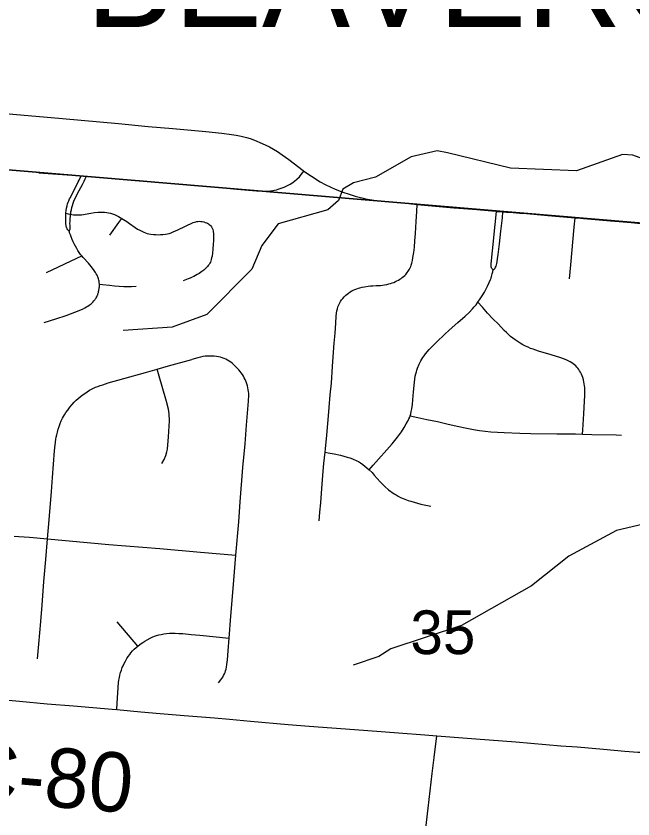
# Model space of a CAD drawing. Extents: x 0 to 34, y 0 to 22.
# Drawn here: x 5.745 to 6.336, y 14.804 to 15.574 of the extents above; entities that cross this region are included whole.
import ezdxf

# ---------------------------------------------------------------- set-up
doc = ezdxf.new("R2010")
doc.units = 0
for name, color, linetype in [('GM_X_City_Street', 7, 'Continuous'), ('GM_X_Corporation', 7, 'Continuous'), ('GM_X_Corporation_Text', 7, 'Continuous'), ('GM_X_County_Road', 7, 'Continuous'), ('GM_X_County_Road_Text', 7, 'Continuous'), ('GM_X_Minor_River', 7, 'Continuous'), ('GM_X_Section_Text', 7, 'Continuous')]:
    doc.layers.add(name, color=color, linetype=linetype)

msp = doc.modelspace()

# ---------------------------------------------------------------- linework, layer by layer
at = {"layer": 'GM_X_City_Street'}
msp.add_line((5.86155, 14.97007), (5.84193, 14.99325), dxfattribs=at)
for points in [[(5.76659, 15.42355), (5.80727, 15.42065), (5.81247, 15.42013), (5.84403, 15.41751), (5.86325, 15.41599), (5.8886, 15.41382), (5.91709, 15.41134), (5.92823, 15.41045), (5.94057, 15.40931), (5.9566, 15.40789), (5.97516, 15.40616), (5.98205, 15.40588), (5.98428, 15.40587), (5.98644, 15.40592), (5.9886, 15.40617), (5.99088, 15.40655), (5.99267, 15.40685), (5.99439, 15.40728), (5.99612, 15.40778), (5.99791, 15.40833), (5.99988, 15.40901), (6.00173, 15.40981), (6.0037, 15.41067), (6.00568, 15.41166), (6.00753, 15.41258), (6.00916, 15.41359), (6.01176, 15.41547), (6.014, 15.41739), (6.0164, 15.41967), (6.01814, 15.42182), (6.02084, 15.42514)], [(5.79274, 15.38468), (5.79298, 15.38724), (5.79331, 15.38946), (5.79376, 15.39168), (5.79431, 15.39372), (5.79479, 15.39525), (5.79535, 15.39665), (5.79618, 15.39842), (5.79703, 15.39995), (5.79816, 15.40208), (5.79962, 15.4049), (5.80451, 15.41482), (5.80527, 15.4163), (5.80727, 15.42065)], [(5.79719, 15.38386), (5.79731, 15.38466), (5.79751, 15.38597), (5.79792, 15.38802), (5.79842, 15.39026), (5.79897, 15.39222), (5.79961, 15.39429), (5.80035, 15.39632), (5.8013, 15.3986), (5.80233, 15.40086), (5.80319, 15.40243), (5.80547, 15.40644), (5.80852, 15.41224), (5.8101, 15.41541), (5.81118, 15.41757), (5.81247, 15.42013)], [(6.0353, 15.09014), (6.03612, 15.09844), (6.03697, 15.10736), (6.03805, 15.12094), (6.03931, 15.1376), (6.03992, 15.145), (6.04099, 15.15577), (6.04133, 15.15912), (6.0427, 15.17205), (6.04436, 15.19055), (6.04495, 15.19855), (6.04605, 15.21086), (6.04704, 15.22196), (6.0481, 15.23789), (6.04885, 15.24715), (6.04988, 15.26012), (6.05059, 15.26999), (6.0512, 15.27926), (6.05166, 15.28599), (6.05199, 15.28885), (6.0524, 15.29127), (6.05285, 15.29325), (6.05335, 15.29493), (6.05388, 15.29646), (6.05444, 15.2977), (6.05511, 15.29904), (6.0559, 15.30027), (6.05692, 15.30168), (6.05813, 15.30311), (6.05943, 15.30467), (6.06103, 15.3062), (6.06215, 15.30713), (6.06354, 15.30825), (6.06514, 15.30936), (6.06668, 15.31037), (6.0681, 15.31108), (6.06966, 15.31179), (6.07145, 15.31242), (6.07305, 15.31292), (6.07449, 15.31333), (6.07654, 15.31386), (6.07893, 15.31432), (6.08222, 15.31481), (6.08452, 15.31509), (6.0869, 15.31527), (6.08998, 15.31534), (6.09266, 15.31542), (6.09418, 15.31555), (6.09594, 15.31575), (6.09808, 15.31608), (6.10037, 15.31653), (6.10224, 15.31699), (6.10379, 15.31743), (6.10522, 15.31791), (6.10687, 15.3185), (6.10855, 15.3192), (6.10991, 15.31986), (6.11136, 15.32065), (6.1127, 15.32142), (6.11408, 15.32235), (6.11504, 15.3231), (6.11606, 15.324), (6.11743, 15.3252), (6.11829, 15.3261), (6.11903, 15.32693), (6.11982, 15.32787), (6.12072, 15.32915), (6.12146, 15.33022), (6.1221, 15.3313), (6.12265, 15.33243), (6.12318, 15.33367), (6.12368, 15.33511), (6.12413, 15.33673), (6.12471, 15.33942), (6.12523, 15.34227), (6.126, 15.34704), (6.12663, 15.35216), (6.12715, 15.35839), (6.12761, 15.36519), (6.12848, 15.37695), (6.12904, 15.38634), (6.12945, 15.39321)], [(5.79587, 15.36752), (5.7949, 15.36835), (5.79437, 15.36896), (5.79393, 15.36965), (5.79359, 15.37041), (5.79329, 15.37127), (5.79305, 15.37201), (5.79289, 15.37283), (5.79268, 15.37452), (5.79249, 15.37692), (5.79244, 15.37862), (5.79253, 15.38181), (5.79274, 15.38468)], [(5.79274, 15.38468), (5.79487, 15.3843), (5.79719, 15.38386)], [(5.79587, 15.36752), (5.79618, 15.36818), (5.79642, 15.3688), (5.79659, 15.3695), (5.79667, 15.37016), (5.79675, 15.37082), (5.79675, 15.37184), (5.79667, 15.37295), (5.79657, 15.37489), (5.79659, 15.37694), (5.79678, 15.37978), (5.79695, 15.3819), (5.79719, 15.38386)], [(5.79719, 15.38386), (5.79844, 15.38361), (5.80002, 15.3833), (5.80162, 15.38314), (5.8033, 15.38306), (5.80532, 15.38309), (5.8075, 15.38335), (5.81668, 15.3849), (5.81999, 15.38532), (5.82352, 15.38562), (5.8257, 15.38573), (5.82793, 15.38577), (5.82974, 15.38569), (5.83174, 15.38551), (5.8336, 15.38519), (5.8355, 15.38477), (5.83742, 15.38416), (5.83913, 15.38353), (5.84116, 15.3826), (5.84312, 15.3816), (5.84474, 15.38071), (5.84638, 15.37973)], [(6.2021, 15.33056), (6.20143, 15.33124), (6.20102, 15.33173), (6.2007, 15.33233), (6.20036, 15.33346), (6.20025, 15.33472), (6.20032, 15.33597), (6.2006, 15.33934), (6.20157, 15.34857), (6.20409, 15.37385), (6.20462, 15.37984), (6.20519, 15.38656)], [(6.2021, 15.33056), (6.20309, 15.33122), (6.20399, 15.33209), (6.20452, 15.33303), (6.20498, 15.33406), (6.20539, 15.33526), (6.20571, 15.33665), (6.206, 15.33825), (6.20645, 15.34117), (6.20703, 15.34516), (6.20815, 15.35529), (6.20964, 15.36756), (6.21082, 15.3779), (6.21102, 15.38035), (6.21149, 15.38605)], [(5.83487, 15.36366), (5.84347, 15.3757), (5.84638, 15.37973)], [(5.84638, 15.37973), (5.84799, 15.37875), (5.8509, 15.37677), (5.85363, 15.37481), (5.85916, 15.37093), (5.86142, 15.36957), (5.86336, 15.36846), (5.86533, 15.36748), (5.86719, 15.36663), (5.86886, 15.366), (5.87059, 15.36545), (5.87223, 15.36506), (5.87411, 15.36476), (5.87651, 15.36443), (5.87896, 15.36423), (5.88103, 15.36415), (5.88321, 15.36422), (5.88555, 15.3644), (5.88804, 15.36467), (5.88987, 15.36501), (5.89156, 15.36541), (5.89356, 15.36604), (5.89556, 15.36678), (5.9, 15.3688), (5.90728, 15.37234), (5.91462, 15.37576), (5.91709, 15.37662), (5.91814, 15.37685), (5.91909, 15.37693), (5.92049, 15.37697), (5.92189, 15.37689), (5.92332, 15.37668), (5.92491, 15.37635), (5.92624, 15.37599), (5.92743, 15.37557), (5.92838, 15.37512), (5.92922, 15.37464), (5.93006, 15.37405), (5.93084, 15.37339), (5.93159, 15.37266), (5.93216, 15.37184), (5.93265, 15.37093), (5.9331, 15.3699), (5.93343, 15.369), (5.93368, 15.36793), (5.93388, 15.36678), (5.93402, 15.36544), (5.93413, 15.36415), (5.93417, 15.36296), (5.93417, 15.36168), (5.93416, 15.36037), (5.93405, 15.35802), (5.93385, 15.35536), (5.93335, 15.35001), (5.93267, 15.34358), (5.93232, 15.34187), (5.93198, 15.34044), (5.93154, 15.33904), (5.93113, 15.33799), (5.93052, 15.33673), (5.92991, 15.33567), (5.92912, 15.33452), (5.92837, 15.33355), (5.92747, 15.33258), (5.92652, 15.33171), (5.92476, 15.33028), (5.92304, 15.32896), (5.92156, 15.32794), (5.92024, 15.32712), (5.91859, 15.32605), (5.91699, 15.32515), (5.91539, 15.32424), (5.91366, 15.32337), (5.91186, 15.32255), (5.90988, 15.32173), (5.90507, 15.31993)], [(6.27522, 15.32185), (6.27644, 15.3353), (6.27984, 15.37133), (6.28069, 15.38034)], [(5.80783, 15.34385), (5.80667, 15.34533), (5.80539, 15.34708), (5.80418, 15.34894), (5.80302, 15.35093), (5.8018, 15.3531), (5.80065, 15.35536), (5.79976, 15.35735), (5.79874, 15.35966), (5.79777, 15.36197), (5.79694, 15.3641), (5.79624, 15.366), (5.79605, 15.3667), (5.79587, 15.36752)], [(5.77407, 15.32788), (5.80299, 15.34152), (5.80783, 15.34385)], [(5.82473, 15.31686), (5.82463, 15.31826), (5.82446, 15.31951), (5.82422, 15.32068), (5.82388, 15.32191), (5.82358, 15.32282), (5.82327, 15.3237), (5.8229, 15.32457), (5.82251, 15.32536), (5.82181, 15.32673), (5.82098, 15.32804), (5.81968, 15.32994), (5.81812, 15.33209), (5.81423, 15.33691), (5.8092, 15.34233), (5.80783, 15.34385)], [(6.0833, 15.13901), (6.08721, 15.14346), (6.10524, 15.16397), (6.1105, 15.17016), (6.11424, 15.1752), (6.11693, 15.17945), (6.11889, 15.18294), (6.12033, 15.18543), (6.12139, 15.18766), (6.12213, 15.18941), (6.12254, 15.19056), (6.1231, 15.19248), (6.12361, 15.19478), (6.12408, 15.19744), (6.12468, 15.20157), (6.12526, 15.20611), (6.12581, 15.21358), (6.1266, 15.22281), (6.12701, 15.22576), (6.12754, 15.22873), (6.12795, 15.23077), (6.12851, 15.23279), (6.12906, 15.23443), (6.12973, 15.23618), (6.13132, 15.24002), (6.13296, 15.24345), (6.13383, 15.24503), (6.1348, 15.24656), (6.13597, 15.24824), (6.1373, 15.25), (6.14096, 15.25411), (6.14788, 15.26118), (6.15588, 15.2689), (6.16002, 15.27263), (6.16834, 15.28005), (6.17527, 15.28624), (6.179, 15.28975), (6.18243, 15.2932), (6.18408, 15.29506), (6.1857, 15.29694), (6.18758, 15.29938), (6.18977, 15.30257), (6.19166, 15.30574), (6.19372, 15.30915), (6.19523, 15.31182), (6.1968, 15.31474), (6.19836, 15.31824), (6.19959, 15.32119), (6.20009, 15.32255), (6.20056, 15.32405), (6.20095, 15.3253), (6.20132, 15.32657), (6.20161, 15.32764), (6.2018, 15.32857), (6.20197, 15.32954), (6.2021, 15.33056)], [(5.77177, 15.28017), (5.78306, 15.28353), (5.79303, 15.28675), (5.80118, 15.28989), (5.80862, 15.29298), (5.81065, 15.29397), (5.81249, 15.29494), (5.81373, 15.29573), (5.81505, 15.29669), (5.81673, 15.29804), (5.81834, 15.29952), (5.81944, 15.30066), (5.8204, 15.30183), (5.82084, 15.30239), (5.82133, 15.30309), (5.82175, 15.30379), (5.82235, 15.30478), (5.82261, 15.30543), (5.8229, 15.30609), (5.82312, 15.30668), (5.82339, 15.30741), (5.82359, 15.3081), (5.82384, 15.30888), (5.82404, 15.30975), (5.82421, 15.31057), (5.82437, 15.31151), (5.8245, 15.31242), (5.82461, 15.31335), (5.82471, 15.31426), (5.82473, 15.31516), (5.82476, 15.316), (5.82473, 15.31686)], [(5.82473, 15.31686), (5.82788, 15.3165), (5.83429, 15.31582), (5.8391, 15.31532), (5.84366, 15.31496), (5.84815, 15.31466), (5.85155, 15.31458), (5.85537, 15.31464), (5.85984, 15.31486)], [(6.28775, 15.17308), (6.288, 15.1772), (6.28896, 15.19257), (6.28959, 15.20473), (6.28984, 15.21024), (6.28992, 15.21324), (6.28997, 15.21597), (6.28992, 15.21772), (6.2898, 15.21928), (6.28951, 15.22125), (6.28918, 15.22317), (6.28869, 15.2252), (6.28806, 15.22725), (6.28742, 15.22898), (6.28673, 15.23063), (6.28585, 15.23235), (6.28501, 15.2338), (6.28417, 15.23502), (6.28326, 15.23623), (6.28232, 15.23732), (6.28124, 15.23842), (6.28018, 15.23938), (6.27896, 15.24035), (6.27751, 15.24135), (6.27594, 15.24232), (6.27406, 15.24332), (6.27216, 15.24422), (6.26966, 15.24529), (6.26704, 15.24623), (6.25763, 15.24913), (6.24571, 15.25262), (6.2429, 15.25347), (6.24033, 15.25435), (6.23789, 15.25528), (6.23567, 15.25626), (6.23304, 15.2575), (6.2306, 15.25879), (6.22794, 15.26029), (6.22521, 15.26203), (6.22309, 15.26346), (6.22109, 15.26492), (6.21878, 15.26675), (6.21673, 15.26854), (6.21479, 15.27045), (6.21271, 15.2725), (6.20711, 15.27833), (6.20189, 15.28368), (6.19681, 15.28909), (6.19189, 15.29461), (6.18758, 15.29938)], [(5.76539, 14.95782), (5.76682, 14.97203), (5.76855, 14.99371), (5.76981, 15.00919), (5.77162, 15.03209), (5.77339, 15.05312), (5.77506, 15.07278), (5.77646, 15.09088), (5.77878, 15.11806), (5.77984, 15.13168), (5.78185, 15.15708), (5.78305, 15.16819), (5.78339, 15.17033), (5.78381, 15.17249), (5.78446, 15.1751), (5.78525, 15.17791), (5.78606, 15.18036), (5.78714, 15.18318), (5.78824, 15.18583), (5.78943, 15.18827), (5.79127, 15.1915), (5.79272, 15.19368), (5.79444, 15.19609), (5.7965, 15.19881), (5.79871, 15.20141), (5.80065, 15.20358), (5.8025, 15.2055), (5.80427, 15.20712), (5.80619, 15.20882), (5.80821, 15.2104), (5.81065, 15.21217), (5.81298, 15.2137), (5.81537, 15.21516), (5.81717, 15.2162), (5.8192, 15.21719), (5.82104, 15.21801), (5.8232, 15.21889), (5.82547, 15.21969), (5.8279, 15.22048), (5.83321, 15.22222), (5.84812, 15.22645), (5.86906, 15.23212), (5.87996, 15.23523), (5.89111, 15.2384), (5.91343, 15.2447)], [(5.93897, 14.93489), (5.94115, 14.93768), (5.9421, 14.939), (5.94296, 14.94036), (5.94378, 14.94175), (5.94463, 14.94338), (5.94522, 14.94471), (5.94573, 14.94627), (5.94621, 14.94804), (5.94661, 14.94987), (5.94699, 14.95235), (5.94744, 14.95675), (5.94818, 14.96547), (5.94908, 14.97764), (5.95077, 14.99875), (5.95297, 15.02536), (5.95566, 15.05702), (5.95825, 15.08908), (5.95967, 15.10827), (5.96233, 15.14106), (5.96433, 15.16392), (5.9658, 15.18185), (5.96761, 15.20474), (5.96791, 15.21032), (5.96791, 15.21212), (5.96773, 15.21404), (5.96749, 15.21565), (5.96713, 15.21758), (5.96663, 15.21939), (5.96605, 15.22128), (5.96536, 15.2233), (5.96446, 15.22532), (5.96364, 15.22699), (5.96278, 15.22864), (5.96178, 15.23016), (5.96073, 15.23175), (5.95957, 15.2332), (5.95836, 15.23462), (5.95718, 15.23595), (5.95586, 15.23727), (5.95397, 15.23912), (5.95225, 15.24068), (5.95056, 15.24212), (5.94921, 15.24306), (5.94768, 15.24402), (5.94608, 15.24479), (5.94429, 15.24559), (5.94255, 15.24619), (5.9407, 15.24674), (5.93885, 15.24713), (5.93702, 15.24747), (5.93478, 15.24771), (5.93269, 15.24786), (5.93042, 15.24792), (5.92835, 15.24783), (5.92619, 15.24767), (5.92403, 15.24732), (5.92167, 15.24685), (5.91918, 15.24626), (5.91343, 15.2447)], [(5.88473, 15.14486), (5.88671, 15.14879), (5.88841, 15.15253), (5.88938, 15.15608), (5.88989, 15.15883), (5.89106, 15.17047), (5.89189, 15.18595), (5.89152, 15.19246), (5.89082, 15.19712), (5.88906, 15.20425), (5.88124, 15.23087), (5.87996, 15.23523)], [(6.12254, 15.19056), (6.12981, 15.18906), (6.13868, 15.18725), (6.14864, 15.1851), (6.15763, 15.18293), (6.16775, 15.1806), (6.17686, 15.17879), (6.18324, 15.17755), (6.189, 15.17659), (6.19434, 15.1759), (6.19989, 15.17537), (6.20621, 15.17488), (6.21254, 15.17455), (6.2276, 15.174), (6.23813, 15.17381), (6.263, 15.17354), (6.28103, 15.17325), (6.28775, 15.17308), (6.29657, 15.17286), (6.32012, 15.17235), (6.32499, 15.17216)], [(6.04099, 15.15577), (6.04408, 15.15521), (6.04988, 15.15412), (6.05578, 15.15285), (6.05904, 15.15206), (6.0622, 15.15116), (6.06479, 15.15034), (6.0672, 15.14953), (6.0687, 15.14894), (6.07013, 15.14829), (6.07157, 15.14754), (6.07293, 15.14679), (6.07494, 15.14549), (6.0771, 15.14399), (6.0791, 15.14257), (6.08108, 15.14097), (6.0833, 15.13901), (6.0861, 15.13622), (6.08818, 15.13384), (6.09386, 15.12733), (6.09822, 15.12304), (6.10195, 15.11989), (6.10741, 15.11596), (6.10912, 15.11484), (6.11108, 15.11379), (6.11348, 15.11254), (6.11603, 15.11141), (6.12056, 15.10967), (6.12334, 15.10876), (6.12655, 15.10786), (6.13279, 15.10613), (6.14247, 15.10402)], [(5.74301, 15.07534), (5.74738, 15.07499), (5.75762, 15.07426), (5.77506, 15.07278), (5.83371, 15.06748), (5.88263, 15.06346), (5.92164, 15.06008), (5.95566, 15.05702)], [(5.84147, 14.90916), (5.84187, 14.91535), (5.84249, 14.92534), (5.84321, 14.9352), (5.84351, 14.93746), (5.84395, 14.94003), (5.84445, 14.94227), (5.8451, 14.94478), (5.84581, 14.94704), (5.84666, 14.9494), (5.84741, 14.95119), (5.84841, 14.95329), (5.84967, 14.95563), (5.85109, 14.9581), (5.85243, 14.96015), (5.85383, 14.96212), (5.85501, 14.96373), (5.85657, 14.96538), (5.85822, 14.96714), (5.86004, 14.9688), (5.86155, 14.97007), (5.86335, 14.97147), (5.8648, 14.97252), (5.86644, 14.97363), (5.86844, 14.97486), (5.87067, 14.97613), (5.87325, 14.97751), (5.87532, 14.97848), (5.87771, 14.97947), (5.87963, 14.98012), (5.88174, 14.98076), (5.88408, 14.98127), (5.88651, 14.98171), (5.88921, 14.98206), (5.89192, 14.98234), (5.89427, 14.98251), (5.89747, 14.98242), (5.90076, 14.98226), (5.90483, 14.98196), (5.91258, 14.9813), (5.92089, 14.98045), (5.94908, 14.97764)]]:
    msp.add_lwpolyline(points, dxfattribs=at)
at = {"layer": 'GM_X_Corporation'}
for points in [[(5.72435, 16.21065), (6.63404, 16.12897), (6.76485, 16.11648), (6.70262, 15.34504), (5.67259, 15.43183)], [(6.70262, 15.34504), (6.61438, 14.34042), (5.59637, 14.4213), (5.67259, 15.43183)]]:
    msp.add_lwpolyline(points, close=True, dxfattribs=at)
at = {"layer": 'GM_X_County_Road'}
for points in [[(5.67585, 15.48556), (5.69897, 15.48377), (5.72497, 15.48127), (5.74165, 15.47964), (5.78929, 15.47537), (5.84316, 15.47061), (5.87161, 15.46793), (5.89509, 15.4658), (5.92661, 15.46302), (5.94208, 15.46145), (5.95138, 15.46027), (5.95576, 15.45955), (5.96063, 15.45855), (5.96576, 15.45723), (5.96933, 15.45616), (5.97353, 15.45473), (5.9809, 15.45156), (5.98768, 15.4482), (5.9953, 15.44377), (6.00002, 15.44064), (6.00616, 15.43627), (6.02001, 15.42573), (6.02084, 15.42514)], [(6.02084, 15.42514), (6.02807, 15.42008), (6.03644, 15.41495), (6.04125, 15.41221), (6.04652, 15.40961), (6.0507, 15.40785), (6.05811, 15.40497), (6.06421, 15.40283), (6.06984, 15.40113), (6.07618, 15.39943), (6.07984, 15.39863), (6.0836, 15.398), (6.09217, 15.39675), (6.10128, 15.39582), (6.11858, 15.39424), (6.12945, 15.39321)], [(6.12945, 15.39321), (6.14332, 15.39189), (6.16436, 15.39002), (6.17365, 15.38926), (6.17798, 15.38891), (6.18664, 15.38817), (6.20082, 15.38693), (6.20519, 15.38656)], [(6.20519, 15.38656), (6.20608, 15.38647), (6.21149, 15.38605), (6.21501, 15.38576), (6.22135, 15.38532), (6.2277, 15.38478), (6.23413, 15.38433), (6.24784, 15.38318), (6.25465, 15.38257), (6.27694, 15.38067), (6.28069, 15.38034)], [(6.28069, 15.38034), (6.28251, 15.38017), (6.2887, 15.37965), (6.30364, 15.37843), (6.31469, 15.37757), (6.32274, 15.37696), (6.33451, 15.37589), (6.34378, 15.37493), (6.35245, 15.3741), (6.36992, 15.3721), (6.38653, 15.37054)], [(5.63159, 14.9275), (5.63559, 14.92682), (5.66092, 14.92472), (5.68755, 14.92252), (5.73085, 14.91874), (5.74818, 14.91727), (5.77479, 14.91487), (5.80006, 14.91268), (5.83702, 14.90954), (5.84147, 14.90916)], [(5.84147, 14.90916), (5.86449, 14.9072), (5.88306, 14.9056), (5.90595, 14.90356), (5.93505, 14.90123), (5.94929, 14.9001), (5.96966, 14.89829), (6.00553, 14.89505), (6.02593, 14.89332), (6.06924, 14.89007), (6.09468, 14.88815), (6.11131, 14.88696), (6.13659, 14.88505), (6.14826, 14.88405)], [(6.1223, 14.65269), (6.12386, 14.66916), (6.12556, 14.68638), (6.12801, 14.70921), (6.13055, 14.73297), (6.13145, 14.74209), (6.13395, 14.76531), (6.13971, 14.81466), (6.14362, 14.84794), (6.14551, 14.86342), (6.14826, 14.88405)], [(6.14826, 14.88405), (6.18568, 14.8812), (6.22373, 14.87823), (6.26707, 14.87456), (6.28254, 14.87341), (6.30793, 14.87144), (6.32832, 14.86946), (6.34067, 14.86856), (6.34561, 14.86833), (6.35487, 14.86812), (6.36159, 14.86854), (6.36695, 14.86952), (6.37055, 14.8702)]]:
    msp.add_lwpolyline(points, dxfattribs=at)
at = {"layer": 'GM_X_Minor_River'}
for points in [[(6.37957, 15.42429), (6.33588, 15.44045), (6.32602, 15.44105), (6.2821, 15.42528), (6.2188, 15.42781), (6.15838, 15.44243), (6.14856, 15.44455), (6.12341, 15.43864), (6.08927, 15.41924), (6.06831, 15.414), (6.05795, 15.40777), (6.05395, 15.39683), (6.04354, 15.38794), (5.99624, 15.37453), (5.98029, 15.35397), (5.97075, 15.33099), (5.92782, 15.28785), (5.89458, 15.27565), (5.84748, 15.2725)], [(6.61244, 15.0139), (6.52722, 15.03221), (6.50448, 15.03308), (6.48049, 15.02829), (6.44627, 15.04386), (6.40077, 15.065), (6.36963, 15.08317), (6.34618, 15.08672), (6.32027, 15.08083), (6.27466, 15.05636), (6.23884, 15.02788), (6.17173, 14.98981), (6.10416, 14.96735), (6.09263, 14.96), (6.06782, 14.9518)]]:
    msp.add_lwpolyline(points, dxfattribs=at)

# ---------------------------------------------------------------- texts
at = {"layer": 'GM_X_Corporation_Text'}
msp.add_text('BEAVERCREEK', height=0.094697, rotation=0.00001, dxfattribs=at).set_placement((5.8116, 15.56299))
at = {"layer": 'GM_X_County_Road_Text'}
msp.add_text('C-80', height=0.056818, rotation=355.26534, dxfattribs=at).set_placement((5.69049, 14.82356))
at = {"layer": 'GM_X_Section_Text'}
msp.add_text('35', height=0.041856, rotation=0.00001, dxfattribs=at).set_placement((6.12281, 14.96238))

doc.saveas('drawing.dxf')
